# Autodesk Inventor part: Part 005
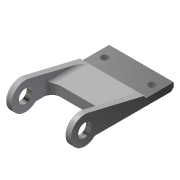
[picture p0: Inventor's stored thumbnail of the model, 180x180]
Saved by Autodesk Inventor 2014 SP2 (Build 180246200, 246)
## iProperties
Created: 2015-03
Part Number: Part 005
Material: Steel
Document SubType Name: Modeling
Designer: SFC
Density: 7.85 g/cm^3
Appearance: Steel
Author: SFC
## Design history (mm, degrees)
sketch "Sketch1"
  geometry: L1 (19, -7)-(19, 0); L2 (19, 0)-(43, 0); L3 (43, 0)-(43, -2); L4 (43, -2)-(64, -2); L5 (64, -2)-(64, -7); L6 (64, -7)-(19, -7); 1 further point
  constraints: 12 end point, 4 parallel, 1 perpendicular, 1 point on line, 1 vertical
  dimensions: "d0" = 19 distance from line of point (0, 0) L1; "d1" = 64 distance from line of L5 point (0, 0); "d2" = 21 distance of L3.end L4.end; "d3" = 5 distance between parallel lines of L6 L4; "d4" = 7 distance of L1.start L1.end
extrude "Extrusion1" new body sketch "Sketch1" stored distance "d5" = 46.5; taper "d6" = 0 deg
fillet "Fillet1" dims "d7" = 2
chamfer "Chamfer1" distance "d8" = 2; stored, may be unused: second distance "d9" = 2, angle "d10" = 45 deg
sketch "Sketch2"
  geometry: L1 (0, 43)-(0, 19) reference; L2 (0, 19)-(7, 19) reference; L3 (7, 19)-(7, 62) reference; L4 (7, 19)-(7, 7.141); L5 (7, 19)-(0, 19); L6 (0, 19)-(0, 43); L7 (0, 43)-(-9.726, 2.326); A1 r 10 centre (0, 0) between (-9.726, 2.326) and (7, 7.141); 1 further point
  constraints: 8 end point, 3 collinear, 2 point on circle, 1 centre point, 1 coincident, 1 tangent
  dimensions: "d11" = 10 radius of A1
extrude "Extrusion2" join sketch "Sketch2" distance "d12" = 4; taper "d13" = 0 deg
fillet "Fillet4" dims "d16" = 2
fillet "Fillet5" dims "d41" = 3
mirror "Mirror2"
sketch "Sketch5"
  geometry: L1 (-19.4, -10)-(19.4, -10); L2 (19.4, -10)-(19.4, 19); L3 (19.4, 19)-(-19.4, 19); L4 (-19.4, 19)-(-19.4, -10); L5 (-19.25, -10)-(-23.25, -10) reference; L6 (-19.25, 19)-(19.25, 19) reference; 2 further points
  constraints: 8 end point, 2 collinear, 2 parallel, 1 horizontal, 1 midpoint, 1 perpendicular, 1 vertical alignment
  dimensions: "d42" = 38.8 distance between parallel lines of L2 L4
extrude "Extrusion4" cut sketch "Sketch5" stored distance "d43" = 4; taper "d44" = 0 deg
fillet "Fillet6" dims "d45" = 6
hole "Hole3" diameter "d48" = 9.5; stored, may be unused: countersink angle "d52" = 90 deg, drill point angle "d54" = 118 deg; dims "d46" = 10, "d47" = 10, "d49" = 6, "d50" = 4, "d51" = 2, "d53" = 8
sketch "Sketch6"
  geometry: L1 (46.5, 0)-(0, 0) reference; L2 (6.25, -9.5)-(40.25, -9.5); L3 (46.5, -2)-(0, -2) reference; 2 further points
  constraints: 2 end point, 1 horizontal alignment, 1 midpoint, 1 parallel, 1 vertical alignment
  dimensions: "d55" = 34 distance of L2.end L2.start; "d56" = 9.5 distance between parallel lines of L1 L2
hole "Hole4" sketch "Sketch6" at (6.25, -9.5), (40.25, -9.5) diameter "d57" = 5.2; stored, may be unused: countersink angle "d61" = 90 deg, drill point angle "d63" = 118 deg; dims "d58" = 6, "d59" = 4, "d60" = 2, "d62" = 8
body "Solid1"
